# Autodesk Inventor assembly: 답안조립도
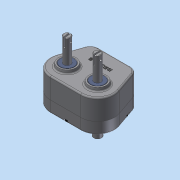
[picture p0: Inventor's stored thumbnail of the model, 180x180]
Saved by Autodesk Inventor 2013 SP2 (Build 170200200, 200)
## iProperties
Created: 2014-12
Part Number: 답안조립도
Document SubType Name: Assembly
Designer: dgall
Author: dgall
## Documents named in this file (13)
- C:\Documents and Settings\dgall\바탕 화면\441208V1042\답안조립도.iam
- C:\Documents and Settings\dgall\바탕 화면\441208V1042\본체.ipt
- C:\Documents and Settings\dgall\바탕 화면\441208V1042\오일시일-D-15.ipt
- C:\Documents and Settings\dgall\바탕 화면\441208V1042\커버.ipt
- C:\Documents and Settings\dgall\바탕 화면\441208V1042\베어링- 6203.ipt
- C:\Documents and Settings\dgall\바탕 화면\441208V1042\오일시일-D-17.ipt
- C:\Documents and Settings\dgall\바탕 화면\441208V1042\베어링- 6202.ipt
- C:\Documents and Settings\dgall\바탕 화면\441208V1042\서브축.ipt
- C:\Documents and Settings\dgall\바탕 화면\441208V1042\키5x5.ipt
- C:\Documents and Settings\dgall\바탕 화면\441208V1042\서브기어.ipt
- C:\Documents and Settings\dgall\바탕 화면\441208V1042\메인축.ipt
- C:\Documents and Settings\dgall\바탕 화면\441208V1042\메인기어.ipt
- C:\Documents and Settings\dgall\바탕 화면\441208V1042\M 5 x 35.ipt
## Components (12 placed, 5 different names)
1. KS B 2804 D D - 15 30 7:1
2. KS B 2804 D D - 15 30 7:2
3. KS B 2023 6203 - 17 x 40 x 12:1
4. KS B 2804 D D - 17 30 8:1
5. KS B 2023 6202 - 15 x 35 x 11:1
6. KS B 2023 6202 - 15 x 35 x 11:2
7. KS B 2023 6203 - 17 x 40 x 12:2
8. KS B 2023 6203 - 17 x 40 x 12:3
9. KS B 2023 6203 - 17 x 40 x 12:4
10. KS B 1003 - 미터 M 5 x 35:1
11. KS B 1003 - 미터 M 5 x 35:2
12. KS B 1003 - 미터 M 5 x 35:3
